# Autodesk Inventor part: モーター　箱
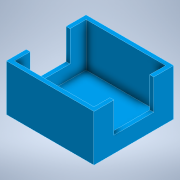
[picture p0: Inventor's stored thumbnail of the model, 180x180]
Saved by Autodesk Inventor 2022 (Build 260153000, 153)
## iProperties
Created: 2024-12
Part Number: モーター　箱
Material: 一般
Document SubType Name: Modeling
Designer: jsat7
Density: 1 g/cm^3
Appearance: 既定
Author: jsat7
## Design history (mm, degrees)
sketch "スケッチ1"
  geometry: L1 (11.871, -8.304)-(-21.129, -8.304); L2 (-21.129, -8.304)-(-21.129, 21.696); L3 (-21.129, 21.696)-(11.871, 21.696); L4 (11.871, 21.696)-(11.871, -8.304); 1 further point
  constraints: 8 end point, 2 parallel, 1 horizontal, 1 perpendicular
  dimensions: "d0" = 33 distance of L1.start L1.end; "d1" = 30 distance of L3.end L1.start
extrude "押し出し1" new body sketch "スケッチ1" distance "d2" = 1; taper "d3" = 0 deg
sketch "スケッチ2"
  geometry: L1 (-10.371, 6.804)-(19.629, 6.804); L2 (19.629, 6.804)-(19.629, -20.196); L3 (19.629, -20.196)-(-10.371, -20.196); L4 (-10.371, -20.196)-(-10.371, 6.804); L5 (21.129, 8.304)-(-11.871, 8.304) reference; L6 (-11.871, 8.304)-(-11.871, -21.696) reference; L7 (-11.871, -21.696)-(21.129, -21.696) reference; L8 (21.129, -21.696)-(21.129, 8.304) reference; 1 further point
  constraints: 8 end point, 2 parallel, 1 horizontal, 1 perpendicular
  dimensions: "d4" = 1.5 distance between parallel lines of L1 L5; "d5" = 1.5 distance between parallel lines of L6 L4; "d6" = 1.5 distance between parallel lines of L7 L3; "d7" = 1.5 distance between parallel lines of L8 L2
extrude "押し出し2" join sketch "スケッチ2" distance "d8" = 16.5; taper "d9" = 0 deg
sketch "スケッチ3"
  geometry: L1 (1.5, 17.5)-(28.5, 17.5) reference; L2 (7.5, 17.5)-(22.5, 17.5); L3 (22.5, 17.5)-(22.5, 6); L4 (22.5, 6)-(7.5, 6); L5 (7.5, 6)-(7.5, 17.5); L6 (0, 0)-(0, 17.5) reference; L7 (30, 0)-(30, 17.5) reference; L8 (0, 0)-(30, 0) reference; 2 further points
  constraints: 8 end point, 2 parallel, 1 horizontal, 1 perpendicular, 1 point on line
  dimensions: "d10" = 7.5 distance between parallel lines of L6 L5; "d11" = 7.5 distance between parallel lines of L7 L3; "d12" = 6 distance between parallel lines of L8 L4
extrude "押し出し3" cut sketch "スケッチ3" distance "d13" = 40; taper "d14" = 0 deg
node "ソリッド1"
